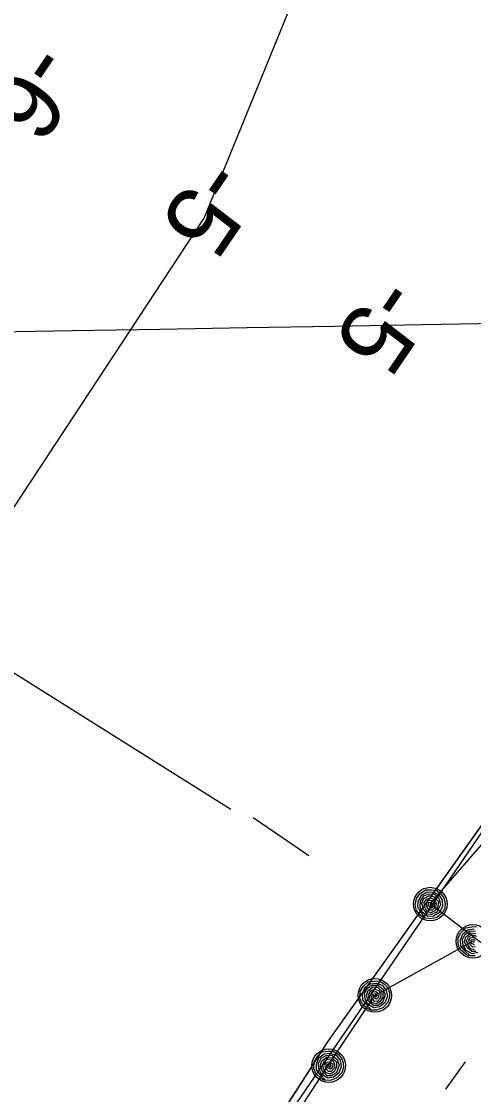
# Model space of a CAD drawing. Extents: x 3905714 to 3926767, y 183354 to 205755.
# Drawn here: x 3918084 to 3918299, y 193081 to 193593 of the extents above; entities that cross this region are included whole.
import ezdxf

# ---------------------------------------------------------------- set-up
doc = ezdxf.new("R2010")
doc.units = 0
for name, color, linetype in [('V-GRID-MAJR', 7, 'Continuous'), ('V-LEVE-TOET', 7, 'Continuous'), ('V-RIVR-EDGE', 7, 'Continuous'), ('V-RIVR-RANG', 7, 'Continuous'), ('V-RRAP-FSHR', 7, 'Continuous'), ('V-TOPO-MINR', 7, 'Continuous'), ('V-TOPO-SHOR', 7, 'Continuous'), ('V-WETL-SWMP', 7, 'Continuous')]:
    doc.layers.add(name, color=color, linetype=linetype)

msp = doc.modelspace()

# ---------------------------------------------------------------- linework, layer by layer
at = {"layer": 'V-GRID-MAJR'}
msp.add_spline([(3911066.23, 193323.42), (3914779.24, 193387.51), (3920105.98, 193480.1), (3922587.21, 193523.5)], degree=3, dxfattribs=at)
at = {"layer": 'V-LEVE-TOET'}
for p, q in [((3918183.82, 193217.17), (3917898.13, 193396.48)), ((3918220.95, 193194.99), (3918194.44, 193213.11))]:
    msp.add_line(p, q, dxfattribs=at)
at = {"layer": 'V-RIVR-EDGE'}
msp.add_lwpolyline([(3919493.03, 195270.35), (3919305.22, 194922.64), (3919123, 194558.19), (3919063.5, 194396.42), (3918673.01, 193834.87), (3918364.35, 193295.63), (3917893.91, 192607.64), (3917620.57, 192168.81), (3917187.32, 191508.71)], dxfattribs=at)
at = {"layer": 'V-RRAP-FSHR'}
for points in [[(3918500.7, 193027.4), (3918466.61, 193048.46), (3918432.53, 193069.52), (3918398.44, 193090.58), (3918364.35, 193111.63), (3918330.26, 193132.69), (3918278.84, 193172.11), (3918310.99, 193209.12), (3918335.37, 193240.76), (3918357.71, 193273.94), (3918380.38, 193307.13), (3918402.37, 193340.32), (3918424.7, 193373.5), (3918445.37, 193407.73), (3918465.38, 193442.36), (3918485.38, 193477), (3918505.39, 193511.64), (3918525.4, 193546.27), (3918545.41, 193580.91)], [(3918276.04, 193165.25), (3918274.38, 193166.49), (3918272.29, 193169.01), (3918271.64, 193171.51), (3918272.2, 193174.68), (3918273.81, 193176.91), (3918276.51, 193178.85), (3918279.42, 193178.85), (3918281.68, 193178.63), (3918283.94, 193176.91), (3918285.35, 193174.81), (3918285.86, 193172.51), (3918285.72, 193170.3), (3918284.64, 193167.92), (3918281.96, 193165.69), (3918278.87, 193164.93), (3918276.49, 193165.29), (3918274.4, 193168.12), (3918272.87, 193170.66), (3918273.11, 193173.45), (3918274.63, 193176.3), (3918277.35, 193177.8), (3918280.36, 193177.74), (3918282.86, 193176.49), (3918284.56, 193173.91), (3918284.73, 193170.94), (3918283.12, 193167.89), (3918280.41, 193166.35), (3918277.62, 193166.13), (3918274.99, 193168.23), (3918273.98, 193170.8), (3918274.15, 193173.64), (3918275.72, 193175.91), (3918278.15, 193176.97), (3918280.89, 193176.69), (3918283.12, 193174.47), (3918283.77, 193171.71), (3918282.03, 193168.23), (3918279.46, 193167.04), (3918277.57, 193167.29), (3918275.6, 193169.63), (3918274.84, 193172.41), (3918275.81, 193174.65), (3918278.47, 193176.13), (3918280.76, 193175.54), (3918282.75, 193173.18), (3918282.46, 193170.78), (3918281.01, 193168.83), (3918279.05, 193167.91), (3918277.14, 193168.68), (3918276.27, 193170.48), (3918275.89, 193172.75), (3918277.14, 193174.42), (3918279, 193175.03), (3918280.99, 193174.12), (3918281.72, 193172.36), (3918281.37, 193170.63), (3918279.71, 193169.15), (3918278.38, 193169.17), (3918277.24, 193170.81), (3918277.02, 193172.72), (3918277.92, 193173.84), (3918279.48, 193173.79), (3918280.85, 193172.51), (3918280.47, 193170.92), (3918279.38, 193170.16), (3918278.05, 193171.13), (3918278.05, 193172.77), (3918279.22, 193172.89), (3918279.75, 193171.88), (3918279.38, 193171.12), (3918278.8, 193171.98)], [(3918297.41, 193147.19), (3918295.57, 193148.17), (3918293.13, 193150.34), (3918292.1, 193152.71), (3918292.17, 193155.92), (3918293.43, 193158.38), (3918295.8, 193160.7), (3918298.67, 193161.15), (3918300.94, 193161.27)], [(3918300.25, 193147.31), (3918297.85, 193147.3), (3918295.35, 193149.78), (3918293.45, 193152.06), (3918293.26, 193154.85), (3918294.33, 193157.9), (3918296.79, 193159.79), (3918299.77, 193160.2)], [(3918301.56, 193148.95), (3918298.84, 193148.31), (3918295.92, 193149.98), (3918294.53, 193152.37), (3918294.27, 193155.2), (3918295.47, 193157.68), (3918297.7, 193159.1), (3918300.46, 193159.24)], [(3918076.7, 192861.53), (3918098.3, 192894.75), (3918120.59, 192927.96), (3918142.66, 192961.32), (3918164.62, 192994.75), (3918186.57, 193028.19), (3918208.52, 193061.63), (3918230.48, 193095.66), (3918252.43, 193128.5), (3918299.14, 193154.3)], [(3918300.51, 193149.48), (3918298.61, 193149.44), (3918296.31, 193151.46), (3918295.13, 193154.09), (3918295.75, 193156.45), (3918298.15, 193158.32), (3918300.5, 193158.08)], [(3918299.98, 193150.29), (3918297.97, 193150.76), (3918296.84, 193152.4), (3918296.12, 193154.58), (3918297.1, 193156.42), (3918298.84, 193157.31), (3918300.94, 193156.72)], [(3918300.44, 193151.61), (3918299.12, 193151.42), (3918297.75, 193152.87), (3918297.23, 193154.73), (3918297.95, 193155.97), (3918299.5, 193156.15)], [(3918299.96, 193152.56), (3918298.49, 193153.31), (3918298.25, 193154.93), (3918299.39, 193155.23), (3918300.06, 193154.31)], [(3918299.81, 193153.5), (3918299.11, 193154.27)], [(3918250.45, 193121.46), (3918248.65, 193122.5), (3918246.28, 193124.75), (3918245.34, 193127.16), (3918245.52, 193130.36), (3918246.85, 193132.77), (3918249.31, 193135.02), (3918252.19, 193135.36), (3918254.46, 193135.41), (3918256.92, 193133.97), (3918258.56, 193132.05), (3918259.34, 193129.83), (3918259.46, 193127.61), (3918258.67, 193125.12), (3918256.27, 193122.6), (3918253.3, 193121.48), (3918250.89, 193121.55), (3918248.48, 193124.11), (3918246.66, 193126.46), (3918246.57, 193129.25), (3918247.74, 193132.26), (3918250.26, 193134.07), (3918253.26, 193134.38), (3918255.89, 193133.42), (3918257.88, 193131.07), (3918258.4, 193128.13), (3918257.17, 193124.92), (3918254.66, 193123.07), (3918251.92, 193122.52), (3918249.06, 193124.29), (3918247.75, 193126.73), (3918247.58, 193129.57), (3918248.87, 193132.01), (3918251.15, 193133.35), (3918253.91, 193133.39), (3918256.38, 193131.45), (3918257.36, 193128.78), (3918256.04, 193125.13), (3918253.63, 193123.64), (3918251.72, 193123.66), (3918249.49, 193125.76), (3918248.41, 193128.43), (3918249.11, 193130.77), (3918251.57, 193132.55), (3918253.92, 193132.23), (3918256.17, 193130.12), (3918256.17, 193127.71), (3918254.96, 193125.6), (3918253.12, 193124.46), (3918251.13, 193125), (3918250.06, 193126.68), (3918249.41, 193128.89), (3918250.46, 193130.69), (3918252.23, 193131.52), (3918254.31, 193130.86), (3918255.25, 193129.19), (3918255.1, 193127.43), (3918253.63, 193125.77), (3918252.31, 193125.62), (3918250.98, 193127.12), (3918250.53, 193128.99), (3918251.29, 193130.21), (3918252.85, 193130.34), (3918254.37, 193129.24), (3918254.18, 193127.62), (3918253.18, 193126.73), (3918251.74, 193127.53), (3918251.55, 193129.16), (3918252.7, 193129.42), (3918253.34, 193128.48), (3918253.07, 193127.68), (3918252.39, 193128.47)], [(3918228.5, 193088.02), (3918226.69, 193089.06), (3918224.33, 193091.32), (3918223.38, 193093.72), (3918223.56, 193096.93), (3918224.9, 193099.34), (3918227.35, 193101.58), (3918230.24, 193101.92), (3918232.51, 193101.97), (3918234.96, 193100.54), (3918236.61, 193098.62), (3918237.39, 193096.39), (3918237.51, 193094.18), (3918236.71, 193091.69), (3918234.32, 193089.16), (3918231.34, 193088.04), (3918228.94, 193088.11), (3918226.53, 193090.67), (3918224.71, 193093.02), (3918224.62, 193095.81), (3918225.79, 193098.82), (3918228.31, 193100.64), (3918231.31, 193100.94), (3918233.94, 193099.99), (3918235.93, 193097.63), (3918236.45, 193094.7), (3918235.21, 193091.48), (3918232.7, 193089.63), (3918229.96, 193089.08), (3918227.1, 193090.86), (3918225.8, 193093.29), (3918225.63, 193096.13), (3918226.92, 193098.57), (3918229.2, 193099.91), (3918231.96, 193099.96), (3918234.43, 193098.02), (3918235.41, 193095.35), (3918234.09, 193091.69), (3918231.68, 193090.2), (3918229.77, 193090.23), (3918227.54, 193092.32), (3918226.46, 193094.99), (3918227.16, 193097.33), (3918229.62, 193099.11), (3918231.96, 193098.79), (3918234.22, 193096.68), (3918234.21, 193094.27), (3918233, 193092.16), (3918231.17, 193091.02), (3918229.18, 193091.56), (3918228.11, 193093.24), (3918227.46, 193095.45), (3918228.5, 193097.25), (3918230.27, 193098.08), (3918232.36, 193097.42), (3918233.29, 193095.75), (3918233.15, 193093.99), (3918231.68, 193092.33), (3918230.36, 193092.18), (3918229.03, 193093.69), (3918228.58, 193095.56), (3918229.34, 193096.77), (3918230.9, 193096.9), (3918232.42, 193095.8), (3918232.23, 193094.18), (3918231.23, 193093.3), (3918229.79, 193094.1), (3918229.6, 193095.73), (3918230.75, 193095.99), (3918231.39, 193095.04), (3918231.11, 193094.24), (3918230.44, 193095.04)]]:
    msp.add_lwpolyline(points, dxfattribs=at)
for centre in [(3918278.84, 193172.01), (3918299.14, 193154.3), (3918252.43, 193128.5), (3918230.48, 193095.07)]:
    msp.add_circle(centre, 8, dxfattribs=at)
at = {"layer": 'V-TOPO-MINR'}
msp.add_lwpolyline([(3917213.53, 191712.34), (3917316.29, 192136.26), (3917674.91, 192748.71), (3917700.38, 192785.64), (3917725.66, 192822.7), (3917750.65, 192859.96), (3917775.45, 192897.35), (3918171.08, 193498.79), (3918258.23, 193712.7), (3918301.06, 193814.36), (3918345.46, 193915.32), (3918392.22, 194015.2), (3918440.56, 194114.36), (3918511.03, 194254.7), (3918525.78, 194282.89), (3918541.16, 194310.72), (3918557.47, 194338.02), (3918574.39, 194364.96), (3919084.15, 195146.63)], dxfattribs=at)
at = {"layer": 'V-TOPO-SHOR'}
msp.add_lwpolyline([(3917580.91, 192095.24), (3917614.08, 192149.13), (3917770.11, 192409.57), (3917907.5, 192616.98), (3917938.89, 192670.08), (3917985.51, 192731.38), (3918099.57, 192904.08), (3918230.43, 193106.83), (3918368.8, 193301.82), (3918407.85, 193366.27), (3918497.71, 193516.49), (3918586.1, 193672.1)], dxfattribs=at)
at = {"layer": 'V-WETL-SWMP'}
for p, q in [((3918230.43, 193106.83), (3918368.8, 193301.82)), ((3918099.58, 192904.08), (3918230.43, 193106.83)), ((3918295.51, 193096.81), (3918286.05, 193083.9))]:
    msp.add_line(p, q, dxfattribs=at)

# ---------------------------------------------------------------- texts
at = {"layer": 'V-RIVR-RANG'}
for s, p in [('-6', (3918088.33, 193584.69)), ('-5', (3918171.56, 193529.25)), ('-5', (3918254.35, 193473.16))]:
    msp.add_text(s, height=33.5, rotation=235.7383, dxfattribs=at).set_placement(p)

doc.saveas('drawing.dxf')
